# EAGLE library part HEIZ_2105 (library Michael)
Platinenlayout für KM271 Platine in Buderus Logamatic 2105 Steuerung
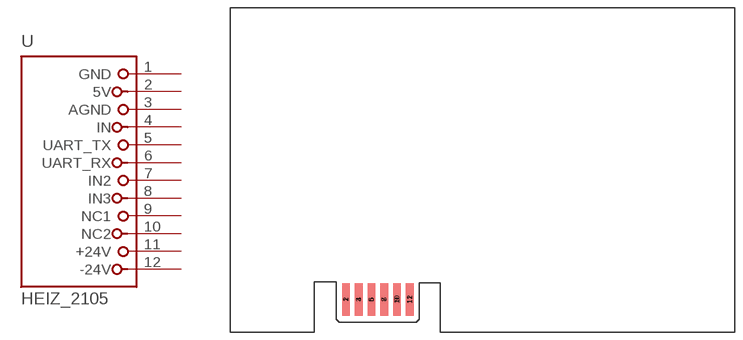
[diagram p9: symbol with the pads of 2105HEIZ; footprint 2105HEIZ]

Designator prefix -

## HEIZ_2105  [2105HEIZ]
1  GND  pwr
2  5V  pwr
3  AGND  pwr
4  IN  in
5  UART_TX  out
6  UART_RX  in
7  IN2  in
8  IN3  in
9  NC1  nc
10  NC2  nc
11  +24V  pwr
12  -24V  pwr

## Footprint 2105HEIZ (pad centres in mm)
Connector für die Heizungssteuerung
smd 1.524 x 6.477 bottom: 1 -77.6,6.54; 3 -75.06,6.54; 5 -72.52,6.54; 7 -69.98,6.54; 9 -67.44,6.54; 11 -64.9,6.54
smd 1.524 x 6.477: 2 -77.6,6.54; 4 -75.06,6.54; 6 -72.52,6.54; 8 -69.98,6.54; 10 -67.44,6.54; 12 -64.9,6.54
